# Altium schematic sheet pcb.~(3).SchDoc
size A4; SheetNumber: 1; SheetTotal: 1
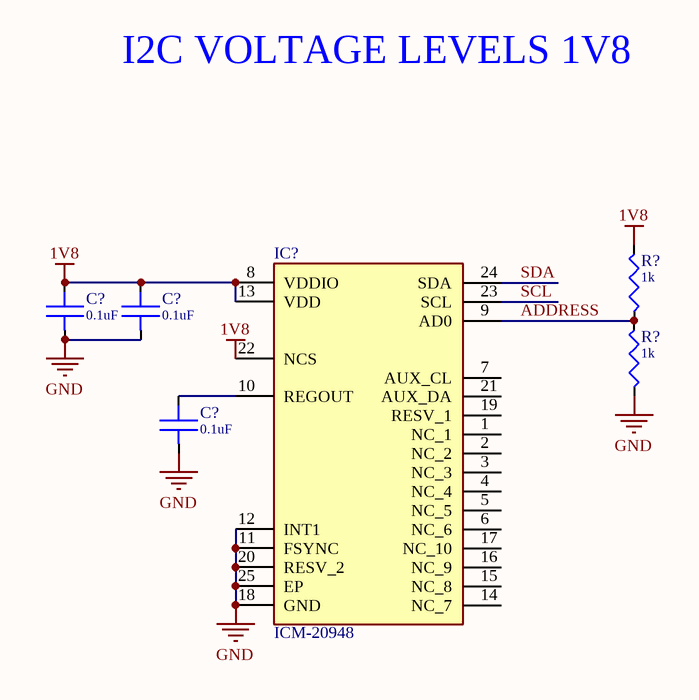
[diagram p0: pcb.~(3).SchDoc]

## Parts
(Parts that share a designator on the sheet are numbered #1, #2 ... from top to bottom, then left to right.)
C?#1  Parameter 1: 0.1uF  [CAPC1608X90N]  (hidden comment: cap0603)
C?#2  Parameter 1: 0.1uF  [CAPC1608X90N]  (hidden comment: cap0603)
C?#3  Parameter 1: 0.1uF  [CAPC1608X90N]  (hidden comment: cap0603)
IC?  ICM-20948  [QFN40P300X300X105-25N-D]
R?#1  Resistance: 1k  [0402resistor]  (hidden comment: res0402)
R?#2  Resistance: 1k  [0402resistor]  (hidden comment: res0402)

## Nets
1V8: C?#1.1 C?#2.1 IC?.8(VDDIO) IC?.13(VDD) IC?.22(NCS) R?#1.1
GND: C?#1.2 C?#2.2 C?#3.2 IC?.11(FSYNC) IC?.12(INT1) IC?.18(GND) IC?.20(RESV_2) IC?.25(EP) R?#2.2
ADDRESS: IC?.9(AD0) R?#1.2 R?#2.1
SCL: IC?.23(SCL)
SDA: IC?.24(SDA)
NetC?#3_1: C?#3.1 IC?.10(REGOUT)

Not connected (* = marked no-connect by the designer): IC? 1(NC_1) 2(NC_2) 3(NC_3) 4(NC_4) 5(NC_5) 6(NC_6) 7(AUX_CL) 14(NC_7) 15(NC_8) 16(NC_9) 17(NC_10) 19(RESV_1) 21(AUX_DA)

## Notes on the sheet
- I2C VOLTAGE LEVELS 1V8

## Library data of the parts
C?#1-C?#3 = cap0603: Capacitor; Manufacturer_Name: SAMSUNG; Manufacturer_Part_Number: CL10A106KP8NNNC
IC? = ICM-20948: Integrated Circuit; Manufacturer_Name: TDK; Description: IMUs - Inertial Measurement Units World's Lowest Power 9-Axis MEMS MotionTracking Device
